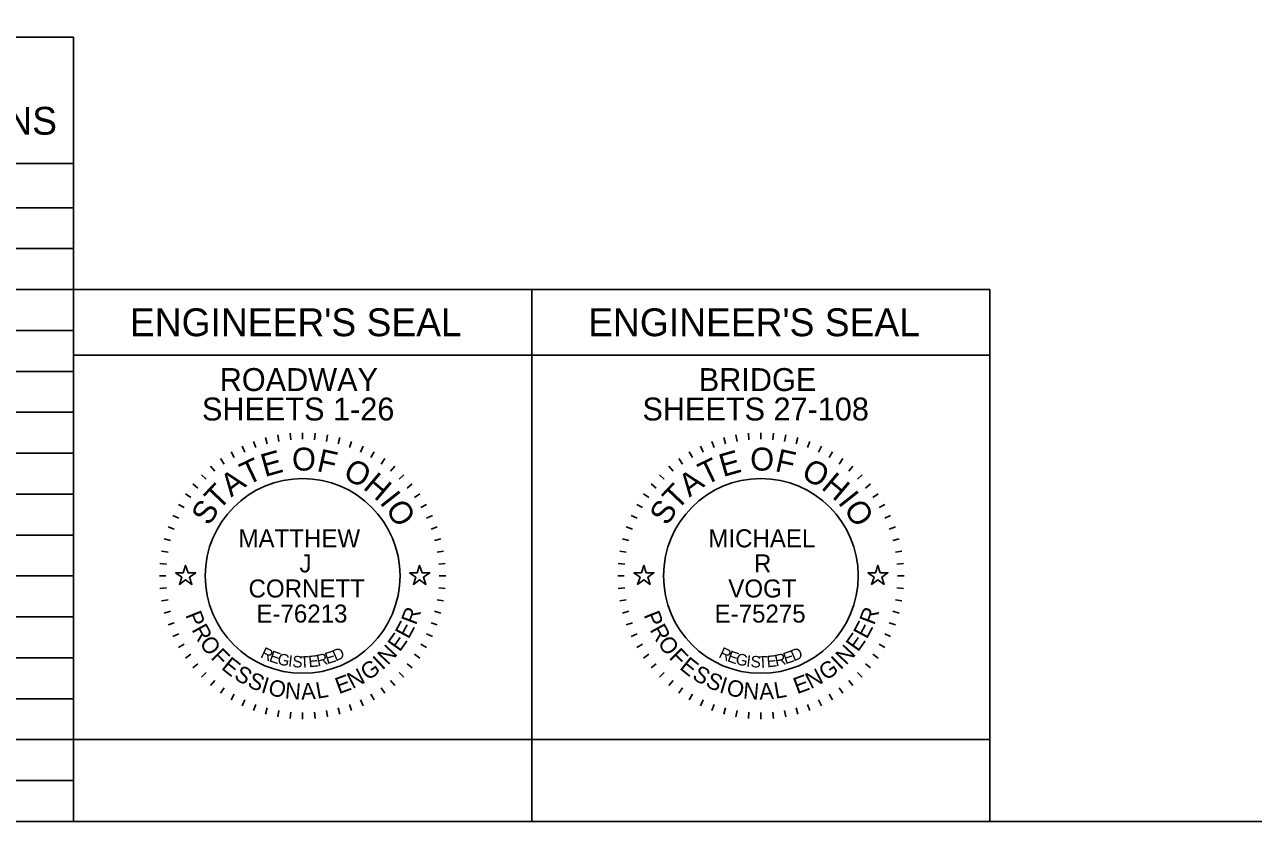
# Model space of a CAD drawing. Extents: x 0 to 34, y -4 to 22.
# Drawn here: x 22.6 to 30.11, y 0.5 to 5.37 of the extents above; entities that cross this region are included whole.
import ezdxf

# ---------------------------------------------------------------- set-up
doc = ezdxf.new("R2010")
doc.units = 0
for name, color, linetype in [('Default', 7, 'Continuous'), ('SH_Border', 7, 'Continuous'), ('SH_Data', 7, 'Continuous'), ('SH_Text', 7, 'Continuous')]:
    doc.layers.add(name, color=color, linetype=linetype)

msp = doc.modelspace()

# ---------------------------------------------------------------- linework, layer by layer
at = {"layer": 'Default'}
for points in [[(23.5276, 2.02), (23.5745, 2.02), (23.589, 2.0645), (23.6035, 2.02), (23.6503, 2.02), (23.6124, 1.9924), (23.6269, 1.9478), (23.589, 1.9754), (23.551, 1.9478), (23.5655, 1.9924)], [(24.9576, 2.02), (25.0045, 2.02), (25.019, 2.0645), (25.0335, 2.02), (25.0803, 2.02), (25.0424, 1.9924), (25.0569, 1.9478), (25.019, 1.9754), (24.981, 1.9478), (24.9955, 1.9924)], [(26.3276, 2.02), (26.3745, 2.02), (26.389, 2.0645), (26.4035, 2.02), (26.4503, 2.02), (26.4124, 1.9924), (26.4269, 1.9478), (26.389, 1.9754), (26.351, 1.9478), (26.3655, 1.9924)], [(27.7576, 2.02), (27.8045, 2.02), (27.819, 2.0645), (27.8335, 2.02), (27.8803, 2.02), (27.8424, 1.9924), (27.8569, 1.9478), (27.819, 1.9754), (27.781, 1.9478), (27.7955, 1.9924)]]:
    msp.add_lwpolyline(points, close=True, dxfattribs=at)
at = {"layer": 'SH_Border'}
msp.add_lwpolyline([(1.5, 21.5), (33.5, 21.5), (33.5, 0.5), (1.5, 0.5)], close=True, dxfattribs=at)
at = {"layer": 'SH_Data'}
for p, q in [((9.454, 5.2917), (22.904, 5.2917)), ((22.904, 0.5), (22.904, 5.2917)), ((9.454, 4.5209), (22.904, 4.5209)), ((9.454, 4.25), (22.904, 4.25)), ((9.454, 4), (22.904, 4)), ((9.454, 3.75), (22.904, 3.75)), ((22.904, 0.5), (22.904, 3.75)), ((22.904, 3.75), (25.704, 3.75)), ((25.704, 3.75), (25.704, 0.5)), ((25.704, 0.5), (25.704, 3.75)), ((25.704, 3.75), (28.504, 3.75)), ((28.504, 3.75), (28.504, 0.5)), ((9.454, 3.5), (22.904, 3.5)), ((22.904, 3.35), (25.704, 3.35)), ((25.704, 3.35), (28.504, 3.35)), ((9.454, 3.25), (22.904, 3.25)), ((9.454, 3), (22.904, 3)), ((24.152, 2.8617), (24.159, 2.8223)), ((24.2277, 2.8717), (24.2312, 2.8318)), ((24.304, 2.875), (24.304, 2.835)), ((24.3802, 2.8717), (24.3767, 2.8318)), ((24.4559, 2.8617), (24.449, 2.8223)), ((26.952, 2.8617), (26.959, 2.8223)), ((27.0277, 2.8717), (27.0312, 2.8318)), ((27.104, 2.875), (27.104, 2.835)), ((27.1802, 2.8717), (27.1767, 2.8318)), ((27.2559, 2.8617), (27.249, 2.8223)), ((23.9342, 2.793), (23.9511, 2.7568)), ((24.0047, 2.8222), (24.0184, 2.7846)), ((24.0775, 2.8452), (24.0878, 2.8065)), ((24.5304, 2.8452), (24.5201, 2.8065)), ((24.6032, 2.8222), (24.5895, 2.7846)), ((24.6737, 2.793), (24.6568, 2.7568)), ((26.7342, 2.793), (26.7511, 2.7568)), ((26.8047, 2.8222), (26.8184, 2.7846)), ((26.8775, 2.8452), (26.8878, 2.8065)), ((27.3304, 2.8452), (27.3201, 2.8065)), ((27.4032, 2.8222), (27.3895, 2.7846)), ((27.4737, 2.793), (27.4568, 2.7568)), ((9.454, 2.75), (22.904, 2.75)), ((23.8021, 2.7168), (23.825, 2.684)), ((23.8665, 2.7578), (23.8865, 2.7231)), ((24.7415, 2.7578), (24.7215, 2.7231)), ((24.8058, 2.7168), (24.7829, 2.684)), ((26.6021, 2.7168), (26.625, 2.684)), ((26.6665, 2.7578), (26.6865, 2.7231)), ((27.5415, 2.7578), (27.5215, 2.7231)), ((27.6058, 2.7168), (27.5829, 2.684)), ((23.7415, 2.6703), (23.7672, 2.6396)), ((24.8664, 2.6703), (24.8407, 2.6396)), ((26.5415, 2.6703), (26.5672, 2.6396)), ((27.6664, 2.6703), (27.6407, 2.6396)), ((23.6337, 2.5624), (23.6643, 2.5367)), ((23.6852, 2.6187), (23.7135, 2.5904)), ((24.9227, 2.6187), (24.8944, 2.5904)), ((24.9742, 2.5624), (24.9436, 2.5367)), ((26.4337, 2.5624), (26.4643, 2.5367)), ((26.4852, 2.6187), (26.5135, 2.5904)), ((27.7227, 2.6187), (27.6944, 2.5904)), ((27.7742, 2.5624), (27.7436, 2.5367)), ((9.454, 2.5), (22.904, 2.5)), ((23.5872, 2.5019), (23.62, 2.4789)), ((25.0207, 2.5019), (24.988, 2.4789)), ((26.3872, 2.5019), (26.42, 2.4789)), ((27.8207, 2.5019), (27.788, 2.4789)), ((23.5462, 2.4375), (23.5808, 2.4175)), ((25.0617, 2.4375), (25.0271, 2.4175)), ((26.3462, 2.4375), (26.3808, 2.4175)), ((27.8617, 2.4375), (27.8271, 2.4175)), ((23.5109, 2.3698), (23.5472, 2.3529)), ((25.097, 2.3698), (25.0607, 2.3529)), ((26.3109, 2.3698), (26.3472, 2.3529)), ((27.897, 2.3698), (27.8607, 2.3529)), ((23.4817, 2.2993), (23.5193, 2.2856)), ((25.1262, 2.2993), (25.0886, 2.2856)), ((26.2817, 2.2993), (26.3193, 2.2856)), ((27.9262, 2.2993), (27.8886, 2.2856)), ((9.454, 2.25), (22.904, 2.25)), ((23.4588, 2.2265), (23.4974, 2.2161)), ((25.1491, 2.2265), (25.1105, 2.2161)), ((26.2588, 2.2265), (26.2974, 2.2161)), ((27.9491, 2.2265), (27.9105, 2.2161)), ((23.4423, 2.1519), (23.4816, 2.145)), ((25.1657, 2.1519), (25.1263, 2.145)), ((26.2423, 2.1519), (26.2816, 2.145)), ((27.9657, 2.1519), (27.9263, 2.145)), ((23.4323, 2.0763), (23.4721, 2.0728)), ((25.1756, 2.0763), (25.1358, 2.0728)), ((26.2323, 2.0763), (26.2721, 2.0728)), ((27.9756, 2.0763), (27.9358, 2.0728)), ((9.454, 2), (22.904, 2)), ((23.429, 2), (23.469, 2)), ((25.179, 2), (25.139, 2)), ((26.229, 2), (26.269, 2)), ((27.979, 2), (27.939, 2)), ((23.4323, 1.9237), (23.4721, 1.9272)), ((25.1756, 1.9237), (25.1358, 1.9272)), ((26.2323, 1.9237), (26.2721, 1.9272)), ((27.9756, 1.9237), (27.9358, 1.9272)), ((23.4423, 1.8481), (23.4816, 1.855)), ((25.1657, 1.8481), (25.1263, 1.855)), ((26.2423, 1.8481), (26.2816, 1.855)), ((27.9657, 1.8481), (27.9263, 1.855)), ((9.454, 1.75), (22.904, 1.75)), ((23.4588, 1.7735), (23.4974, 1.7839)), ((25.1491, 1.7735), (25.1105, 1.7839)), ((26.2588, 1.7735), (26.2974, 1.7839)), ((27.9491, 1.7735), (27.9105, 1.7839)), ((23.4817, 1.7007), (23.5193, 1.7144)), ((25.1262, 1.7007), (25.0886, 1.7144)), ((26.2817, 1.7007), (26.3193, 1.7144)), ((27.9262, 1.7007), (27.8886, 1.7144)), ((23.5109, 1.6302), (23.5472, 1.6471)), ((23.5462, 1.5625), (23.5808, 1.5825)), ((25.0617, 1.5625), (25.0271, 1.5825)), ((25.097, 1.6302), (25.0607, 1.6471)), ((26.3109, 1.6302), (26.3472, 1.6471)), ((26.3462, 1.5625), (26.3808, 1.5825)), ((27.8617, 1.5625), (27.8271, 1.5825)), ((27.897, 1.6302), (27.8607, 1.6471)), ((23.5872, 1.4981), (23.62, 1.5211)), ((25.0207, 1.4981), (24.988, 1.5211)), ((26.3872, 1.4981), (26.42, 1.5211)), ((27.8207, 1.4981), (27.788, 1.5211)), ((9.454, 1.5), (22.904, 1.5)), ((23.6337, 1.4376), (23.6643, 1.4633)), ((24.9742, 1.4376), (24.9436, 1.4633)), ((26.4337, 1.4376), (26.4643, 1.4633)), ((27.7742, 1.4376), (27.7436, 1.4633)), ((23.6852, 1.3813), (23.7135, 1.4096)), ((23.7415, 1.3297), (23.7672, 1.3604)), ((24.8664, 1.3297), (24.8407, 1.3604)), ((24.9227, 1.3813), (24.8944, 1.4096)), ((26.4852, 1.3813), (26.5135, 1.4096)), ((26.5415, 1.3297), (26.5672, 1.3604)), ((27.6664, 1.3297), (27.6407, 1.3604)), ((27.7227, 1.3813), (27.6944, 1.4096)), ((23.8021, 1.2832), (23.825, 1.316)), ((23.8665, 1.2422), (23.8865, 1.2769)), ((24.7415, 1.2422), (24.7215, 1.2769)), ((24.8058, 1.2832), (24.7829, 1.316)), ((26.6021, 1.2832), (26.625, 1.316)), ((26.6665, 1.2422), (26.6865, 1.2769)), ((27.5415, 1.2422), (27.5215, 1.2769)), ((27.6058, 1.2832), (27.5829, 1.316)), ((9.454, 1.25), (22.904, 1.25)), ((23.9342, 1.207), (23.9511, 1.2432)), ((24.0047, 1.1778), (24.0184, 1.2154)), ((24.6032, 1.1778), (24.5895, 1.2154)), ((24.6737, 1.207), (24.6568, 1.2432)), ((26.7342, 1.207), (26.7511, 1.2432)), ((26.8047, 1.1778), (26.8184, 1.2154)), ((27.4032, 1.1778), (27.3895, 1.2154)), ((27.4737, 1.207), (27.4568, 1.2432)), ((24.0775, 1.1548), (24.0878, 1.1935)), ((24.152, 1.1383), (24.159, 1.1777)), ((24.2277, 1.1283), (24.2312, 1.1682)), ((24.304, 1.125), (24.304, 1.165)), ((24.3802, 1.1283), (24.3767, 1.1682)), ((24.4559, 1.1383), (24.449, 1.1777)), ((24.5304, 1.1548), (24.5201, 1.1935)), ((26.8775, 1.1548), (26.8878, 1.1935)), ((26.952, 1.1383), (26.959, 1.1777)), ((27.0277, 1.1283), (27.0312, 1.1682)), ((27.104, 1.125), (27.104, 1.165)), ((27.1802, 1.1283), (27.1767, 1.1682)), ((27.2559, 1.1383), (27.249, 1.1777)), ((27.3304, 1.1548), (27.3201, 1.1935)), ((9.454, 1), (22.904, 1)), ((9.454, 0.75), (22.904, 0.75)), ((22.904, 0.5), (25.704, 0.5)), ((25.704, 0.5), (28.504, 0.5))]:
    msp.add_line(p, q, dxfattribs=at)
for points in [[(22.904, 0.5), (22.904, 1), (25.704, 1), (25.704, 0.5)], [(25.704, 0.5), (25.704, 1), (28.504, 1), (28.504, 0.5)]]:
    msp.add_lwpolyline(points, close=True, dxfattribs=at)
for centre in [(24.304, 2), (27.104, 2)]:
    msp.add_circle(centre, 0.595, dxfattribs=at)

# ---------------------------------------------------------------- texts
for s, height, p in [("ENGINEER'S SEAL", 0.17, (23.2487, 3.465)), ("ENGINEER'S SEAL", 0.17, (26.0487, 3.465)), ('ROADWAY', 0.14, (23.7972, 3.13)), ('BRIDGE', 0.14, (26.7245, 3.13)), ('SHEETS 1-26', 0.14, (23.6886, 2.95)), ('SHEETS 27-108', 0.14, (26.3802, 2.95)), ('MATTHEW ', 0.11, (23.9117, 2.1749)), ('MICHAEL', 0.11, (26.7829, 2.1749)), ('J', 0.11, (24.2847, 2.0216)), ('R', 0.11, (27.0617, 2.0216)), ('CORNETT', 0.11, (23.9735, 1.8684)), ('VOGT', 0.11, (26.9049, 1.8684)), ('E-76213', 0.11, (24.0216, 1.7151)), ('E-75275', 0.11, (26.8213, 1.7151))]:
    msp.add_text(s, height=height, dxfattribs=at).set_placement(p)
for s, height, rotation, p in [('O', 0.14, 359.78119, (24.2387, 2.6443)), ('O', 0.14, 359.78119, (27.0387, 2.6443)), ('T', 0.14, 25.71674, (23.9656, 2.5518)), ('E', 0.14, 15.75706, (24.0724, 2.6038)), ('F', 0.14, 347.43619, (24.385, 2.6417)), ('O', 0.14, 332.25863, (24.5438, 2.6015)), ('T', 0.14, 25.71674, (26.7656, 2.5518)), ('E', 0.14, 15.75706, (26.8724, 2.6038)), ('F', 0.14, 347.43619, (27.185, 2.6417)), ('O', 0.14, 332.25863, (27.3438, 2.6015)), ('A', 0.14, 36.47472, (23.8674, 2.4781)), ('H', 0.14, 319.91363, (24.6671, 2.5361)), ('A', 0.14, 36.47472, (26.6674, 2.4781)), ('H', 0.14, 319.91363, (27.4671, 2.5361)), ('T', 0.14, 46.4344, (23.7923, 2.3964)), ('T', 0.14, 46.4344, (26.5923, 2.3964)), ('I', 0.14, 308.36695, (24.7704, 2.4483)), ('I', 0.14, 308.36695, (27.5704, 2.4483)), ('S', 0.14, 57.19238, (23.7321, 2.3014)), ('O', 0.14, 303.14906, (24.8061, 2.4089)), ('S', 0.14, 57.19238, (26.5321, 2.3014)), ('O', 0.14, 303.14906, (27.6061, 2.4089)), ('R', 0.1, 69.23216, (24.9959, 1.6954)), ('R', 0.1, 69.23216, (27.7959, 1.6954)), ('P', 0.1, 291.49398, (23.5862, 1.7621)), ('E', 0.1, 61.99508, (24.9516, 1.6098)), ('P', 0.1, 291.49398, (26.3862, 1.7621)), ('E', 0.1, 61.99508, (27.7516, 1.6098)), ('R', 0.1, 298.73106, (23.6229, 1.6717)), ('E', 0.1, 54.75801, (24.8973, 1.5314)), ('R', 0.1, 298.73106, (26.4229, 1.6717)), ('E', 0.1, 54.75801, (27.6973, 1.5314)), ('O', 0.1, 306.46664, (23.6694, 1.5883)), ('N', 0.1, 47.02243, (24.8242, 1.4508)), ('O', 0.1, 306.46664, (26.4694, 1.5883)), ('N', 0.1, 47.02243, (27.6242, 1.4508)), ('F', 0.1, 314.7068, (23.7383, 1.4983)), ('E', 0.1, 321.43929, (23.8018, 1.4348)), ('R', 0.07, 334.48695, (24.0414, 1.5051)), ('E', 0.07, 341.03996, (24.0946, 1.4801)), ('G', 0.07, 347.47515, (24.1454, 1.4618)), ('I', 0.07, 353.78581, (24.213, 1.4468)), ('S', 0.07, 356.89262, (24.2397, 1.4429)), ('T', 0.07, 3.00609, (24.2897, 1.4387)), ('E', 0.07, 6.01169, (24.3429, 1.4412)), ('R', 0.07, 11.91844, (24.3965, 1.4474)), ('E', 0.07, 17.68363, (24.4537, 1.4602)), ('D', 0.07, 23.30524, (24.505, 1.477)), ('I', 0.1, 43.28703, (24.7908, 1.4214)), ('F', 0.1, 314.7068, (26.5383, 1.4983)), ('E', 0.1, 321.43929, (26.6018, 1.4348)), ('R', 0.07, 334.48695, (26.8414, 1.5051)), ('E', 0.07, 341.03996, (26.8946, 1.4801)), ('G', 0.07, 347.47515, (26.9454, 1.4618)), ('I', 0.07, 353.78581, (27.013, 1.4468)), ('S', 0.07, 356.89262, (27.0397, 1.4429)), ('T', 0.07, 3.00609, (27.0897, 1.4387)), ('E', 0.07, 6.01169, (27.1429, 1.4412)), ('R', 0.07, 11.91844, (27.1965, 1.4474)), ('E', 0.07, 17.68363, (27.2537, 1.4602)), ('D', 0.07, 23.30524, (27.305, 1.477)), ('I', 0.1, 43.28703, (27.5908, 1.4214)), ('S', 0.1, 328.67637, (23.8783, 1.3752)), ('N', 0.1, 27.31129, (24.6084, 1.3075)), ('G', 0.1, 35.04687, (24.702, 1.357)), ('S', 0.1, 328.67637, (26.6783, 1.3752)), ('N', 0.1, 27.31129, (27.4084, 1.3075)), ('G', 0.1, 35.04687, (27.502, 1.357)), ('S', 0.1, 335.91345, (23.9604, 1.3266)), ('I', 0.1, 343.15053, (24.0446, 1.2897)), ('O', 0.1, 346.88592, (24.0878, 1.2751)), ('L', 0.1, 10.09874, (24.3933, 1.249)), ('E', 0.1, 20.07421, (24.5252, 1.277)), ('S', 0.1, 335.91345, (26.7604, 1.3266)), ('I', 0.1, 343.15053, (26.8446, 1.2897)), ('O', 0.1, 346.88592, (26.8878, 1.2751)), ('L', 0.1, 10.09874, (27.1933, 1.249)), ('E', 0.1, 20.07421, (27.3252, 1.277)), ('N', 0.1, 355.12608, (24.1928, 1.2517)), ('A', 0.1, 2.86166, (24.2962, 1.2437)), ('N', 0.1, 355.12608, (26.9928, 1.2517)), ('A', 0.1, 2.86166, (27.0962, 1.2437))]:
    msp.add_text(s, height=height, rotation=rotation, dxfattribs=at).set_placement(p)
at = {"layer": 'SH_Text'}
msp.add_text('PROVISIONS', height=0.17, dxfattribs=at).set_placement((21.3882, 4.6963))

doc.saveas('drawing.dxf')
